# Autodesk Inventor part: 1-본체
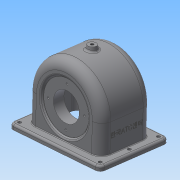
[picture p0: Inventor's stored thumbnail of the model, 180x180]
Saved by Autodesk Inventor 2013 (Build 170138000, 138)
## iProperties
Created: 2015-09
Part Number: 1-본체
Material: 일반
Document SubType Name: Modeling
Designer: ST
Density: 1 g/cm^3
Author: ST
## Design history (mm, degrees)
sketch "스케치1"
  geometry: L1 (-57, 47)-(-57, 0); L2 (57, 47)-(57, 0); L3 (-57, 0)-(57, 0); A1 r 57 centre (0, 47) between (57, 47) and (-57, 47); 3 further points
  constraints: 6 end point, 2 coincident, 2 point on circle, 2 tangent, 1 centre point, 1 midpoint, 1 parallel, 1 perpendicular, 1 vertical, 1 vertical alignment
  dimensions: "d23" = 114 diameter of A1; "d28" = 47 distance of A1.centre point (0, 0)
extrude "돌출5" new body sketch "스케치1" distance "d29" = 77; taper "d30" = 0 deg
feature "쉘2" dims "d31" = 5
sketch "스케치6"
  geometry: L1 (109, 5)-(5, 5) reference; L2 (5, 5)-(5, 72) reference; L3 (5, 72)-(109, 72) reference; L4 (109, 72)-(109, 5) reference; L5 (114, 0)-(0, 0) reference; L6 (0, 0)-(0, 77) reference; L7 (127, -13.5)-(127, 90.5); L8 (127, 90.5)-(-13, 90.5); L9 (-13, 90.5)-(-13, -13.5); L10 (-13, -13.5)-(127, -13.5); 5 further points
  constraints: 8 end point, 4 midpoint, 2 horizontal, 2 vertical, 1 horizontal alignment, 1 vertical alignment
  dimensions: "d32" = 104 distance of L8.end L9.end; "d34" = 140 distance of L7.end L8.end
extrude "돌출6" join sketch "스케치6" distance "d35" = 7; taper "d36" = 0 deg
sketch "스케치7"
  geometry: C1 r 31 at (0, 47); A1 r 57 centre (0, 47) between (57, 47) and (-57, 47) reference; 1 further point
  constraints: 1 centre point, 1 coincident
  dimensions: "d37" = 62 diameter of C1
extrude "돌출7" join sketch "스케치7" distance "d39" = 10; taper "d40" = 0 deg
node "작업 평면1"
sketch "스케치12"
  geometry: L1 (70, 90.5)-(-70, 90.5) reference; L2 (-31, -10)-(31, -10) reference; C1 r 6 at (0, 37); 1 further point
  constraints: 1 centre point, 1 vertical alignment
  dimensions: "d71" = 12 diameter of C1; "d94" = 47 distance from line of L2 C1.centre
extrude "돌출10" join sketch "스케치12" stored distance "d72" = 13; taper "d73" = 10 deg
sketch "스케치13"
  geometry: C1 r 6 at (0, 0) reference; 2 further points
  constraints: 1 coincident
hole "구멍1" sketch "스케치13" at (0, 0) diameter "d74" = 4.459; stored, may be unused: countersink angle "d78" = 90 deg, drill point angle "d80" = 118 deg; dims "d75" = 6, "d76" = 4, "d77" = 2, "d79" = 8
sketch "스케치14"
  geometry: L1 (127, 13.5)-(-13, 13.5) reference; L2 (-13, 13.5)-(-13, -90.5) reference; C1 r 2.5 at (-5, -82.5); C2 r 2.5 at (-5, -38.5); C3 r 2.5 at (-5, 5.5); C4 r 2.5 at (119, 5.5); C5 r 2.5 at (119, -38.5); C6 r 2.5 at (119, -82.5); 1 further point
  constraints: 6 centre point, 5 equal radius, 4 vertical alignment, 3 horizontal alignment
  dimensions: "d81" = 44 distance of C2.centre C3.centre; "d83" = 44 distance of C1.centre C2.centre; "d84" = 8 distance from line of C3.centre L1; "d85" = 124 distance of C4.centre C3.centre; "d86" = 8 distance from line of C3.centre L2; "d87" = 5 diameter of C1
extrude "돌출11" cut sketch "스케치14" stored distance "d88" = 13; taper "d89" = 0 deg
fillet "모깎기2" dims "d90" = 7
fillet "모깎기3" dims "d91" = 3
fillet "모깎기4" dims "d92" = 14
sketch "스케치15"
  geometry: C1 r 31 at (0, 0) reference; C2 r 20 at (0, 0); 1 further point
  constraints: 1 centre point, 1 coincident
  dimensions: "d95" = 40 diameter of C2
extrude "돌출12" cut sketch "스케치15" stored distance "d97" = 13; taper "d98" = 0 deg
sketch "스케치16"
  geometry: C1 r 20 at (0, 0) reference; C2 r 31 at (0, 0) reference; A1 r 24 centre (0, 0) between (0, 24) and (0, -24); 3 further points
  constraints: 4 point on circle, 2 horizontal alignment, 2 vertical alignment, 1 centre point, 1 coincident
  dimensions: "d99" = 48 diameter of A1
hole "구멍2" sketch "스케치16" at (0, 24), (0, -24), (-24, 0), (24, 0) diameter "d101" = 2.459; stored, may be unused: countersink angle "d105" = 90 deg, drill point angle "d107" = 118 deg; dims "d102" = 6, "d103" = 4, "d104" = 2, "d106" = 8
sketch "스케치20"
  geometry: L1 (-63, 40)-(-63, 0) reference; L2 (-69.5, -7)-(-76.5, -7) reference; 2 further points
  constraints: 1 other
  dimensions: "d123" = 38.5 distance from line of point (-24.5, 23) L1; "d124" = 30 distance from line of point (-24.5, 23) L2
feature "엠보싱1" sketch "스케치20" dims "d23" = 114, "d28" = 47, "d125" = 0.5, "d126" = 0
fillet "모깎기5" dims "d127" = 1
fillet "모깎기6" dims "d128" = 9
fillet "모깎기7" dims "d142" = 3
sketch "스케치25"
  geometry: L1 (47, 91.743)-(47, -40.519); L2 (75, 58)-(47, 58); L3 (47, 72)-(47, 63) reference; L4 (47, 63)-(47, 63) reference; L5 (47, 72)-(47, 63) reference; L6 (47, 72)-(47, 72) reference; L7 (47, 72)-(47, 58); L8 (47, 72)-(86.747, 72); L9 (86.747, 72)-(75, 58); 1 further point
  constraints: 10 end point, 2 perpendicular, 1 point on line, 1 vertical
  dimensions: "d157" = 47 distance from line of point (0, 0) L1; "d158" = 56 diameter of L2.start L1; "d170" = 50 deg angle of L2 L9; "d171" = 14 vertical distance of L8.end L2.start
revolve "회전4" sketch "스케치25" stored, may be unused: angle "d161" = 90 deg
sketch "스케치28"
  geometry: L1 (84.416, 77)-(81.899, 74); L2 (47, 77)-(47, -10); L3 (47, 77)-(90, 77) reference; L4 (67, -10)-(27, -10) reference; L5 (86.747, 72)-(75, 58) reference; L6 (81.899, 74)-(47, 74); L7 (84.416, 77)-(47, 77); L8 (47, 77)-(47, 74); 1 further point
  constraints: 10 end point, 3 point on line, 1 collinear, 1 midpoint, 1 perpendicular, 1 vertical
  dimensions: "d172" = 47 horizontal distance of point (0, 0) L2.end; "d175" = 5 distance between parallel lines of L1 L5; "d176" = 3 distance between parallel lines of L3 L6
revolve "회전6" sketch "스케치28" stored, may be unused: angle "d177" = 90 deg
fillet "모깎기9" dims "d186" = 0.5
fillet "모깎기10" dims "d187" = 3
chamfer "모따기1" distance "d197" = 1; stored, may be unused: second distance "d198" = 2, angle "d199" = 45 deg
sketch "스케치32"
  geometry: C1 r 28 at (0, 0) reference; C2 r 20 at (0, 0); 1 further point
  constraints: 1 centre point, 1 coincident
  dimensions: "d200" = 40 diameter of C2
extrude "돌출20" cut sketch "스케치32" distance "d203" = 16; taper "d204" = 0 deg
sketch "스케치33"
  geometry: C1 r 20 at (0, 0) reference; C2 r 34.665 at (0, 0) reference; A1 r 28 centre (0, 0) between (0, 28) and (0, -28); 3 further points
  constraints: 4 point on circle, 2 horizontal alignment, 2 vertical alignment, 1 centre point, 1 coincident
  dimensions: "d205" = 56 diameter of A1
hole "구멍5" sketch "스케치33" at (0, 28), (0, -28), (-28, 0), (28, 0) diameter "d208" = 3; stored, may be unused: countersink angle "d212" = 90 deg, drill point angle "d214" = 118 deg; dims "d209" = 6, "d210" = 4, "d211" = 2, "d213" = 8
node "솔리드2"
node "투영된 루프2"
